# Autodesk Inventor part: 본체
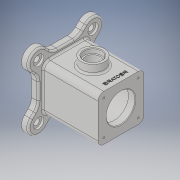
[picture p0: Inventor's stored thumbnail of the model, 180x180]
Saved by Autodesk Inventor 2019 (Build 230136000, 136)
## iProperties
Created: 2021-01
Part Number: 본체
Material: 일반
Document SubType Name: Modeling
Designer: 3dpro9
Density: 1 g/cm^3
Appearance: 기본값
Mass: 385.865 g
Surface Area: 854.376 cm^2
Volume: 385.865 cm^3
Author: 3dpro9
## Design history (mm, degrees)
sketch "스케치1"
  geometry: L1 (48, 48)-(-48, -48); L2 (-48, 48)-(48, -48); L3 (48, -22.544)-(48, 22.544); L4 (34.648, 60.104)-(22.544, 48); L5 (60.104, 34.648)-(48, 22.544); L6 (60.104, -34.648)-(48, -22.544); L7 (34.648, -60.104)-(22.544, -48); L8 (-48, -22.544)-(-60.104, -34.648); L9 (-22.544, -48)-(-34.648, -60.104); L10 (-22.544, 48)-(-34.648, 60.104); L11 (-48, 22.544)-(-60.104, 34.648); L12 (-22.544, -48)-(22.544, -48); L13 (-48, 22.544)-(-48, -22.544); L14 (22.544, 48)-(-22.544, 48); L15 (0, -101.965)-(0, 101.965) reference; L16 (-101.965, 0)-(101.965, 0) reference; A1 r 18 centre (47.376, 47.376) between (60.104, 34.648) and (34.648, 60.104); A2 r 18 centre (47.376, -47.376) between (34.648, -60.104) and (60.104, -34.648); A3 r 18 centre (-47.376, 47.376) between (-34.648, 60.104) and (-60.104, 34.648); A4 r 18 centre (-47.376, -47.376) between (-60.104, -34.648) and (-34.648, -60.104); A5 r 67 centre (0, 0) between (47.376, -47.376) and (47.376, 47.376); 1 further point
  constraints: 28 end point, 12 point on circle, 8 tangent, 6 parallel, 5 centre point, 4 point on line, 3 equal radius, 2 midpoint, 1 coincident, 1 horizontal, 1 perpendicular, 2 other
  dimensions: "d0" = 96 distance of L2.start L1.end; "d1" = 96 distance of L1.end L2.end; "d2" = 134 diameter of A5; "d3" = 36 diameter of A2; "d4" = 45 deg angle of L16 L2; "d5" = 45 deg angle of L1 L16; "d6" = 96 distance between parallel lines of L12 L14; "d7" = 96 distance between parallel lines of L3 L13; "d8" = 135 deg angle of L3 L5; "d9" = 135 deg angle of L6 L3; "d10" = 135 deg angle of L12 L9; "d11" = 135 deg angle of L14 L10
extrude "돌출1" new body sketch "스케치1" distance "d12" = 12; taper "d13" = 0 deg
sketch "스케치2"
  geometry: L1 (-40, 40)-(40, 40); L2 (40, 40)-(40, -40); L3 (40, -40)-(-40, -40); L4 (-40, -40)-(-40, 40); L5 (-40, 40)-(40, -40); L6 (40, 40)-(-40, -40); 1 further point
  constraints: 12 end point, 2 midpoint, 2 parallel, 1 horizontal, 1 perpendicular
  dimensions: "d14" = 80 distance of L2.end L3.end; "d15" = 80 distance of L1.end L2.end
extrude "돌출2" join sketch "스케치2" distance "d16" = 96; taper "d17" = 0 deg
sketch "스케치3"
  geometry: L1 (122.903, 0)-(-21.468, 0); L2 (108, 25)-(96, 25); L3 (96, 25)-(96, 35); L4 (96, 35)-(12, 35); L5 (12, 35)-(12, 25); L6 (12, 25)-(0, 25); L7 (108, 40)-(108, -40) reference; L8 (0, -22.544)-(0, 22.544) reference; L9 (0, 25)-(0, 0); L10 (108, 25)-(108, 0); 1 further point
  constraints: 16 end point, 5 point on line, 4 perpendicular, 2 horizontal, 1 collinear, 1 midpoint, 1 vertical alignment
  dimensions: "d18" = 50 diameter of L2 L1; "d19" = 70 diameter of L4 L1; "d20" = 12 distance of L5.end L6.end; "d21" = 12 distance of L2.start L2.end
revolve "회전1" sketch "스케치3" stored, may be unused: angle "d22" = 90 deg
sketch "스케치4"
  geometry: L1 (-12, 17.456)-(-12, 62.544) reference; C1 r 20 at (47, 40); 2 further points
  constraints: 1 centre point, 1 horizontal alignment, 1 midpoint
  dimensions: "d23" = 40 diameter of C1; "d24" = 59 distance from line of L1 C1.centre
extrude "돌출3" join sketch "스케치4" distance "d25" = 15; taper "d26" = 0 deg
sketch "스케치5"
  geometry: C1 r 20 at (0, 0) reference; 2 further points
  constraints: 1 coincident
sketch "스케치7"
  geometry: L1 (91.527, 0)-(-91.527, 0) reference; L2 (0, -91.527)-(0, 91.527) reference; L3 (30, 30)-(0, 0); L4 (-30, 30)-(0, 0); L5 (0, 0)-(-30, -30); L6 (0, 0)-(30, -30); C1 r 25 at (0, 0) reference; 1 further point
  constraints: 8 end point, 2 horizontal alignment, 2 vertical alignment, 1 midpoint
  dimensions: "d34" = 45 deg angle of L2 L3; "d35" = 45 deg angle of L2 L4; "d36" = 45 deg angle of L2 L5; "d37" = 45 deg angle of L6 L2; "d38" = 60 distance of L6.end L5.end
hole "구멍2" sketch "스케치7" at (30, 30), (30, -30), (-30, -30), (-30, 30) diameter "d39" = 3.242; stored, may be unused: countersink angle "d43" = 90 deg, drill point angle "d45" = 118 deg; dims "d40" = 8, "d41" = 30, "d42" = 8, "d44" = 10
node "작업 평면1"
sketch "스케치8"
  geometry: A1 r 18 centre (-47.376, 47.376) between (-34.648, 60.104) and (-60.104, 34.648) reference; 2 further points
  constraints: 1 coincident
hole "구멍3" sketch "스케치8" at (-47.376, 47.376) diameter "d47" = 10; stored, may be unused: countersink angle "d51" = 90 deg, drill point angle "d53" = 118 deg; dims "d48" = 8, "d49" = 18, "d50" = 4, "d52" = 10
hole "구멍4" sketch "스케치5" diameter "d54" = 25; stored, may be unused: countersink angle "d58" = 90 deg, drill point angle "d60" = 0 deg; dims "d55" = 8, "d56" = 30, "d57" = 8, "d59" = 10
sketch "스케치9"
  geometry: L1 (96, 80)-(96, 0) reference; L2 (-33.6, 40)-(117.6, 40) reference; 2 further points
  constraints: 1 point on line, 1 other
  dimensions: "d61" = 10 distance from line of point (86, 40) L1
feature "엠보싱1" sketch "스케치9" dims "d9" = 135 deg, "d62" = 0.5, "d63" = 0
fillet "모깎기1" dims "d64" = 10
fillet "모깎기2" dims "d65" = 20
fillet "모깎기3" dims "d66" = 3
chamfer "모따기1" distance "d67" = 1; stored, may be unused: second distance "d68" = 2, angle "d69" = 45 deg
chamfer "모따기2" distance "d70" = 1; stored, may be unused: second distance "d71" = 2, angle "d72" = 45 deg
chamfer "모따기3" distance "d73" = 1; stored, may be unused: second distance "d74" = 2, angle "d75" = 45 deg
fillet "모깎기4" dims "d76" = 3
fillet "모깎기5" dims "d77" = 3
fillet "모깎기6" dims "d78" = 3
node "솔리드1"
mirror "미러1"
mirror "미러2"
mirror "미러3"
other parameters: "d46" = -54
